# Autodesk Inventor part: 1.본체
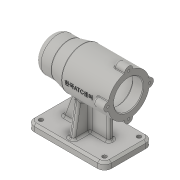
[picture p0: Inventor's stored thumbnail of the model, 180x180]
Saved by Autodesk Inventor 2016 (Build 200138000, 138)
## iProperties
Created: 2019-07
Part Number: 1.본체
Material: 일반
Document SubType Name: Modeling
Designer: 605-11
Density: 1 g/cm^3
Appearance: 기본값
Author: 605-11
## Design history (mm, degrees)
sketch "스케치1"
  geometry: L1 (-56, 0)-(56, 0); L2 (56, 21)-(41, 21); L3 (41, 21)-(41, 24); L4 (41, 24)-(-13, 24); L5 (-13, 24)-(-13, 21); L6 (-13, 21)-(-25, 21); L7 (-25, 21)-(-25, 17.5); L8 (-25, 17.5)-(-43, 17.5); L9 (-43, 17.5)-(-43, 16); L10 (-43, 16)-(-47, 16); L11 (-47, 16)-(-47, 10.5); L12 (-47, 10.5)-(-50, 10.5); L13 (-50, 10.5)-(-50, 0); L14 (-56, 0)-(-56, 25); L15 (-56, 25)-(-31, 25); L16 (-31, 25)-(-11, 30); L17 (-11, 30)-(56, 30); L18 (56, 30)-(56, 21); 1 further point
  constraints: 36 end point, 13 perpendicular, 3 horizontal, 1 midpoint, 1 point on line, 1 vertical, 1 vertical alignment
  dimensions: "d0" = 112 distance of L1.start L1.end; "d1" = 56 distance of point (0, 0) L1.start (= 0.5 x d0); "d2" = 15 distance of L2.start L2.end; "d3" = 54 distance of L3.end L4.end; "d4" = 12 distance of L5.end L6.end; "d5" = 18 distance of L7.end L8.end; "d6" = 4 distance of L9.end L10.end; "d7" = 3 distance of L11.end L12.end; "d9" = 25 distance of L14.end L15.end; "d10" = 45 horizontal distance of L16.end L14.end; "d11" = 42 diameter of L2 L1; "d12" = 21 diameter of L12 L1; "d13" = 32 diameter of L10 L1; "d14" = 35 diameter of L8 L1; "d15" = 50 diameter of L15 L1; "d17" = 42 diameter of L6 L1; "d18" = 48 diameter of L4 L1; "d21" = 60 diameter of L17 L1
revolve "회전1" sketch "스케치1" stored, may be unused: angle "d22" = 90 deg
node "작업 평면1"
sketch "스케치2"
  geometry: L1 (56, -35)-(-56, -35); L2 (-56, -35)-(-56, 35); L3 (-56, 35)-(56, 35); L4 (56, 35)-(56, -35); 3 further points
  constraints: 8 end point, 2 midpoint, 2 parallel, 1 horizontal, 1 horizontal alignment, 1 perpendicular, 1 vertical alignment
  dimensions: "d24" = 112 distance of L2.end L3.end; "d25" = 70 distance of L1.end L2.end
extrude "돌출1" join sketch "스케치2" distance "d26" = 10; taper "d27" = 0 deg
fillet "모깎기1" dims "d28" = 10
sketch "스케치3"
  geometry: L1 (46, -70)-(-46, -70) reference; L2 (-56, -70)-(-46, -70) reference; L3 (46, -70)-(56, -70) reference; L4 (-11, -30)-(56, -30) reference; L5 (-31, -25)-(-11, -30) reference; L6 (-36, -70)-(-20.074, -26.243); L7 (31, -70)-(31, -26.243); L8 (-56, -80)-(-56, -70) reference; L9 (-20.074, -26.243)-(31, -26.243); L10 (-36, -70)-(31, -70); 1 further point
  constraints: 8 end point, 2 point on line, 1 collinear, 1 horizontal, 1 perpendicular
  dimensions: "d29" = 25 distance of L3.end L7.start; "d30" = 20 distance from line of L8 L6.start; "d31" = 110 deg angle of L6 L1; "d32" = 51.07373 distance of L6.end L7.end
extrude "돌출2" join sketch "스케치3" stored distance "d33" = 8; taper "d34" = 0 deg
sketch "스케치4"
  geometry: L1 (-27.341, 4)-(-29.732, 4) reference; L2 (-29.732, -4)-(-27.341, -4) reference; L3 (-70, -25)-(-70, -35) reference; L4 (-70, -25)-(-70, 25) reference; L5 (-70, 35)-(-70, 25) reference; L6 (-70, -28)-(-22.666, -19.654); C1 r 25 at (0, 0) reference; A1 r 30 centre (0, 0) between (-29.732, -4) and (-29.732, 4) reference; A2 r 30 centre (0, 0) between (-29.732, -4) and (-29.732, 4) reference; 2 further points; 1 other entity
  constraints: 2 end point, 1 point on circle, 1 point on line, 1 other
  dimensions: "d35" = 7 distance of L3.end L6.start; "d36" = 100 deg angle of L3 L6
feature "리브1" sketch "스케치4" dims "d37" = 1, "d38" = 8, "d39" = 0, "d40" = 0, "d41" = 1, "d42" = 1
sketch "스케치5"
  geometry: A1 r 30 centre (0, 0) between (4, -29.732) and (-4, -29.732) reference; A2 r 30 centre (0, 0) between (4, -29.732) and (-4, -29.732) reference; A3 r 6 centre (0, 30) between (5.97, 29.4) and (-5.97, 29.4); 1 further point
  constraints: 5 point on circle, 1 centre point, 1 vertical alignment
  dimensions: "d43" = 60 diameter of A1 (derived); "d45" = 6 radius of A3
extrude "돌출3" join sketch "스케치5" distance "d46" = 16; taper "d47" = 0 deg
sketch "스케치6"
  geometry: A1 r 6 centre (0, 0) between (5.97, -0.6) and (-5.97, -0.6) reference; 1 further point
hole "구멍1" sketch "스케치6" at (0, 0) diameter "d48" = 3.242; stored, may be unused: countersink angle "d52" = 90 deg, drill point angle "d54" = 120 deg; dims "d49" = 8, "d50" = 4, "d51" = 2, "d53" = 11
sketch "스케치7"
  geometry: C1 r 3 at (-46, 25); A1 r 10 centre (-46, 25) between (-46, 35) and (-56, 25) reference; A2 r 10 centre (46, 25) between (56, 25) and (46, 35) reference; A3 r 10 centre (46, -25) between (46, -35) and (56, -25) reference; A4 r 10 centre (-46, -25) between (-56, -25) and (-46, -35) reference; 1 further point
  constraints: 1 centre point, 1 coincident
  dimensions: "d58" = 6 diameter of C1; "d59" = 92 distance of A2.centre A1.centre (derived); "d60" = 50 distance of A4.centre A1.centre (derived)
extrude "돌출4" cut sketch "스케치7" stored distance "d61" = 16; taper "d62" = 0 deg
chamfer "모따기1" distance "d69" = 3; stored, may be unused: second distance "d70" = 2, angle "d71" = 45 deg
chamfer "모따기2" distance "d72" = 1; stored, may be unused: second distance "d73" = 2, angle "d74" = 45 deg
fillet "모깎기2" dims "d75" = 3
fillet "모깎기3" dims "d76" = 0.3
fillet "모깎기4" dims "d77" = 10
fillet "모깎기5" dims "d78" = 3
fillet "모깎기6" dims "d79" = 1
fillet "모깎기7" dims "d80" = 3
fillet "모깎기8" dims "d81" = 1
fillet "모깎기9" dims "d82" = 3
fillet "모깎기10" dims "d83" = 1
fillet "모깎기11" dims "d84" = 3
fillet "모깎기12" dims "d85" = 3
fillet "모깎기13" dims "d86" = 3
fillet "모깎기14" dims "d87" = 3
node "작업 평면2"
sketch "스케치8"
  geometry: L1 (33.5, 30.171)-(33.5, 36) reference; 2 further points
  constraints: 1 horizontal alignment, 1 other
  dimensions: "d88" = 42 distance from line of L1 point (-8.5, 0)
feature "엠보싱1" sketch "스케치8" dims "d0" = 112, "d89" = 0.5, "d90" = 0
node "솔리드1"
mirror "대칭1"
pattern_circular "원형 패턴1" dims angle "d56" = 360 deg
pattern_linear "직사각형 패턴1" dims "d65" = 92 (= d59)
node "투영된 루프1"
